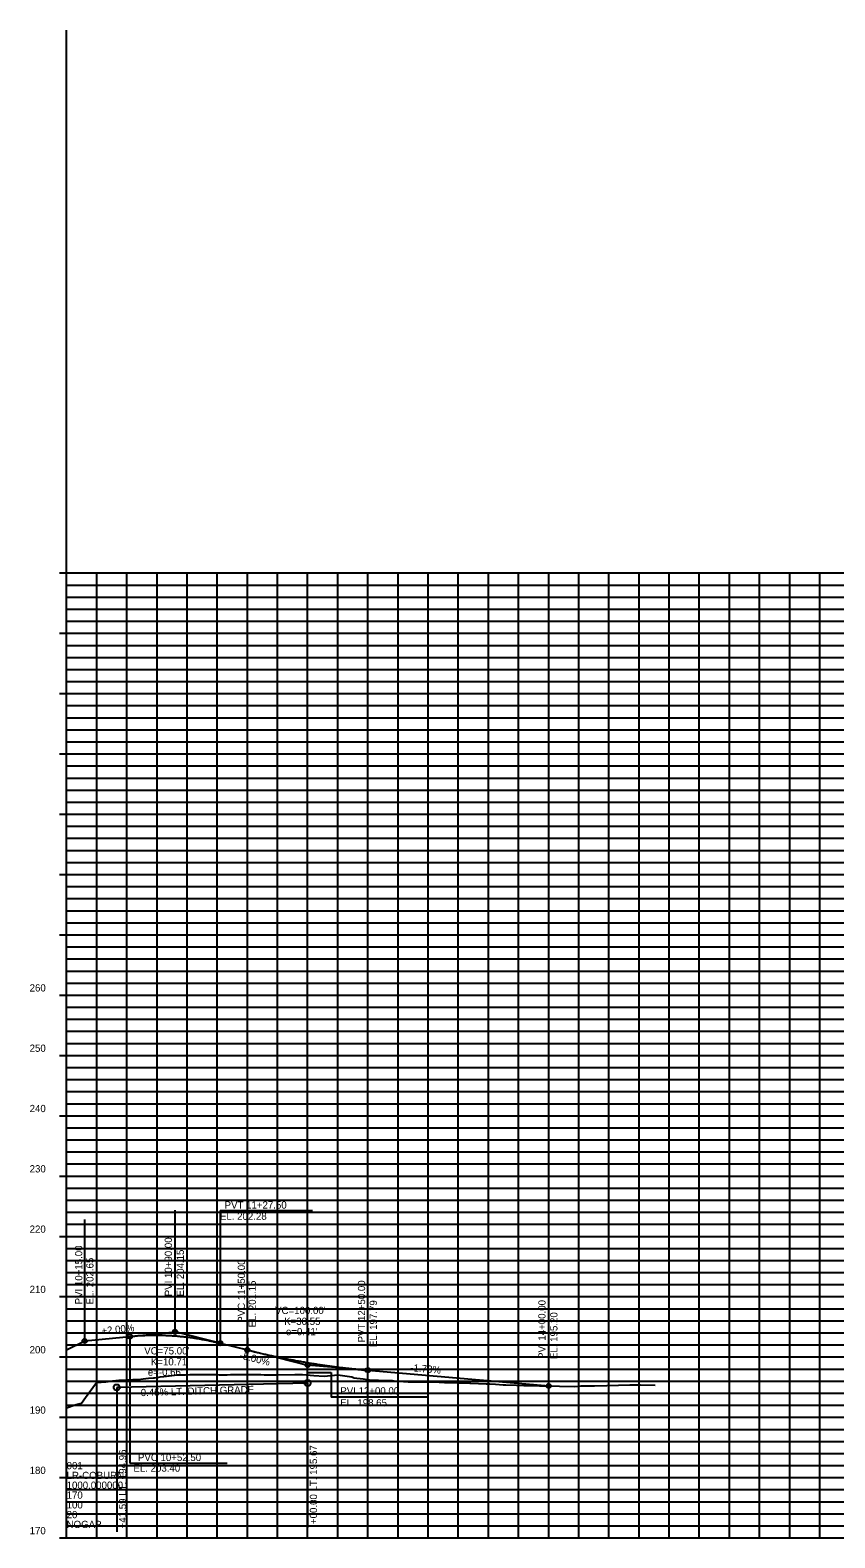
# Model space of a CAD drawing. Extents: x 1384498 to 1391279, y 1965973 to 1976560.
# Drawn here: x 1388619 to 1389286, y 1971310 to 1972560 of the extents above; entities that cross this region are included whole.
import ezdxf

# ---------------------------------------------------------------- set-up
doc = ezdxf.new("R2010")
doc.units = 0
for name, color, linetype in [('63', 7, 'Continuous'), ('Default', 7, 'Continuous'), ('R_Axis_Annotation', 7, 'Continuous'), ('R_Exist Surface', 7, 'Continuous'), ('R_Grid', 7, 'Continuous'), ('R_Grid Annot', 7, 'Continuous'), ('R_Grid_Minor', 7, 'Continuous'), ('R_Vert Alg', 7, 'Continuous'), ('R_Vert Alg Annot', 7, 'Continuous')]:
    doc.layers.add(name, color=color, linetype=linetype)

msp = doc.modelspace()

# ---------------------------------------------------------------- linework, layer by layer
at = {"layer": 'Default'}
msp.add_line((1388648.8, 1971309.8), (1388648.8, 1972559.8), dxfattribs=at)
at = {"layer": 'R_Exist Surface'}
for points in [[(1388648.8, 1971417.6), (1388656.8, 1971420.3), (1388661.1, 1971421.5), (1388664.5, 1971426.1), (1388673.5, 1971438.5), (1388681.3, 1971439.3), (1388686.8, 1971439.9), (1388692.4, 1971440.6), (1388695.1, 1971440.7), (1388698.9, 1971440.9), (1388699.4, 1971440.9), (1388703.8, 1971441), (1388707.9, 1971441.1), (1388708.1, 1971441.2), (1388712.4, 1971441.6), (1388716.7, 1971442.1), (1388721, 1971442.4), (1388721.6, 1971442.5), (1388724.3, 1971442.8), (1388725.3, 1971443), (1388726.4, 1971443.2), (1388729.6, 1971443.6), (1388733.9, 1971444.2), (1388738.2, 1971444.7), (1388740.5, 1971444.9), (1388742.5, 1971444.9), (1388745.9, 1971445), (1388746.8, 1971445), (1388747.5, 1971445), (1388751.1, 1971445.2), (1388751.3, 1971445.2), (1388754.2, 1971445.3), (1388755.5, 1971445.3), (1388757.6, 1971445.4), (1388759.8, 1971445.4), (1388761.1, 1971445.4), (1388764.1, 1971445.4), (1388768.4, 1971445.3), (1388772.7, 1971445.2), (1388775.5, 1971445.1), (1388776.4, 1971445.1), (1388777.1, 1971445.1), (1388777.4, 1971445.1), (1388777.8, 1971445.1), (1388782.1, 1971445.1), (1388784.7, 1971445.2), (1388786.9, 1971445.2), (1388791.6, 1971445.2), (1388791.6, 1971445.2), (1388791.7, 1971445.2), (1388796.2, 1971445.2), (1388798.3, 1971445.3), (1388800.8, 1971445.3), (1388804.9, 1971445.3), (1388805.5, 1971445.3), (1388806.7, 1971445.3), (1388809.3, 1971445.2), (1388810, 1971445.2), (1388812.8, 1971445.1), (1388814.6, 1971445.1), (1388816.3, 1971445), (1388819.1, 1971445), (1388819.8, 1971445), (1388822.3, 1971445), (1388823.2, 1971445), (1388823.4, 1971445), (1388838.2, 1971445.2), (1388841.8, 1971445.2), (1388844.6, 1971445.2), (1388853.8, 1971444.3), (1388862.5, 1971443.8), (1388873.8, 1971445.1), (1388885.5, 1971443.3), (1388886.1, 1971443), (1388886.9, 1971442.7), (1388887.2, 1971442.5), (1388895, 1971441.6), (1388902.2, 1971440.7), (1388907.6, 1971440.5), (1388912, 1971440.3), (1388917.3, 1971440.3), (1388918.8, 1971440.2), (1388920.2, 1971440.1), (1388932.3, 1971439.2), (1388932.7, 1971439.2), (1388939.4, 1971439.1), (1388945.3, 1971439.1), (1388947.4, 1971439.1), (1388957.9, 1971438.8), (1388962.4, 1971438.6), (1388968, 1971438.5), (1388968.4, 1971438.5), (1388968.7, 1971438.5), (1388973.7, 1971438.4), (1388976.5, 1971438.4), (1388983.5, 1971438.2), (1388984.2, 1971438.2), (1388997, 1971437.4), (1388997.8, 1971437.5), (1388998.6, 1971437.5), (1389000.1, 1971437.4)], [(1389000.1, 1971437.4), (1389004.6, 1971437.2), (1389011.1, 1971436.8), (1389013.3, 1971436.7), (1389022, 1971436.3), (1389028.3, 1971436.1), (1389031.6, 1971436.1), (1389034.7, 1971436.1), (1389041.1, 1971436), (1389041.5, 1971436), (1389042.9, 1971436), (1389043.5, 1971436), (1389057.8, 1971435.6), (1389070.2, 1971435.4), (1389075.4, 1971436), (1389086.8, 1971436), (1389097, 1971436.1), (1389106.8, 1971436.5), (1389116.1, 1971436.6), (1389125.1, 1971436.6), (1389137.2, 1971436.5)]]:
    msp.add_lwpolyline(points, dxfattribs=at)
at = {"layer": 'R_Grid'}
for p, q in [((1388648.8, 1971309.8), (1388648.8, 1972109.8)), ((1388648.8, 1972109.8), (1391248.8, 1972109.8)), ((1388648.8, 1972109.8), (1391248.8, 1972109.8)), ((1388748.8, 1971309.8), (1388748.8, 1972109.8)), ((1388848.8, 1971309.8), (1388848.8, 1972109.8)), ((1388948.8, 1971309.8), (1388948.8, 1972109.8)), ((1389048.8, 1971309.8), (1389048.8, 1972109.8)), ((1389148.8, 1971309.8), (1389148.8, 1972109.8)), ((1389248.8, 1971309.8), (1389248.8, 1972109.8)), ((1388648.8, 1972059.8), (1391248.8, 1972059.8)), ((1388648.8, 1972009.8), (1391248.8, 1972009.8)), ((1388648.8, 1971959.8), (1391248.8, 1971959.8)), ((1388648.8, 1971909.8), (1391248.8, 1971909.8)), ((1388648.8, 1971859.8), (1391248.8, 1971859.8)), ((1388648.8, 1971809.8), (1391248.8, 1971809.8)), ((1388648.8, 1971759.8), (1391248.8, 1971759.8)), ((1388648.8, 1971709.8), (1391248.8, 1971709.8)), ((1388648.8, 1971659.8), (1391248.8, 1971659.8)), ((1388648.8, 1971609.8), (1391248.8, 1971609.8)), ((1388648.8, 1971559.8), (1391248.8, 1971559.8)), ((1388648.8, 1971509.8), (1391248.8, 1971509.8)), ((1388648.8, 1971459.8), (1391248.8, 1971459.8)), ((1388648.8, 1971409.8), (1391248.8, 1971409.8)), ((1388648.8, 1971359.8), (1391248.8, 1971359.8)), ((1388648.8, 1971309.8), (1391248.8, 1971309.8))]:
    msp.add_line(p, q, dxfattribs=at)
at = {"layer": 'R_Grid Annot'}
for p, q in [((1388642.8, 1972109.8), (1388648.8, 1972109.8)), ((1388642.8, 1972109.8), (1388648.8, 1972109.8)), ((1388648.8, 1972099.8), (1388651.8, 1972099.8)), ((1388648.8, 1972089.8), (1388651.8, 1972089.8)), ((1388648.8, 1972079.8), (1388651.8, 1972079.8)), ((1388648.8, 1972069.8), (1388651.8, 1972069.8)), ((1388642.8, 1972059.8), (1388648.8, 1972059.8)), ((1388648.8, 1972049.8), (1388651.8, 1972049.8)), ((1388648.8, 1972039.8), (1388651.8, 1972039.8)), ((1388648.8, 1972029.8), (1388651.8, 1972029.8)), ((1388648.8, 1972019.8), (1388651.8, 1972019.8)), ((1388642.8, 1972009.8), (1388648.8, 1972009.8)), ((1388648.8, 1971999.8), (1388651.8, 1971999.8)), ((1388648.8, 1971989.8), (1388651.8, 1971989.8)), ((1388648.8, 1971979.8), (1388651.8, 1971979.8)), ((1388648.8, 1971969.8), (1388651.8, 1971969.8)), ((1388642.8, 1971959.8), (1388648.8, 1971959.8)), ((1388648.8, 1971949.8), (1388651.8, 1971949.8)), ((1388648.8, 1971939.8), (1388651.8, 1971939.8)), ((1388648.8, 1971929.8), (1388651.8, 1971929.8)), ((1388648.8, 1971919.8), (1388651.8, 1971919.8)), ((1388642.8, 1971909.8), (1388648.8, 1971909.8)), ((1388648.8, 1971899.8), (1388651.8, 1971899.8)), ((1388648.8, 1971889.8), (1388651.8, 1971889.8)), ((1388648.8, 1971879.8), (1388651.8, 1971879.8)), ((1388648.8, 1971869.8), (1388651.8, 1971869.8)), ((1388642.8, 1971859.8), (1388648.8, 1971859.8)), ((1388648.8, 1971849.8), (1388651.8, 1971849.8)), ((1388648.8, 1971839.8), (1388651.8, 1971839.8)), ((1388648.8, 1971829.8), (1388651.8, 1971829.8)), ((1388648.8, 1971819.8), (1388651.8, 1971819.8)), ((1388642.8, 1971809.8), (1388648.8, 1971809.8)), ((1388648.8, 1971799.8), (1388651.8, 1971799.8)), ((1388648.8, 1971789.8), (1388651.8, 1971789.8)), ((1388648.8, 1971779.8), (1388651.8, 1971779.8)), ((1388648.8, 1971769.8), (1388651.8, 1971769.8)), ((1388642.8, 1971759.8), (1388648.8, 1971759.8)), ((1388648.8, 1971749.8), (1388651.8, 1971749.8)), ((1388648.8, 1971739.8), (1388651.8, 1971739.8)), ((1388648.8, 1971729.8), (1388651.8, 1971729.8)), ((1388648.8, 1971719.8), (1388651.8, 1971719.8)), ((1388642.8, 1971709.8), (1388648.8, 1971709.8)), ((1388648.8, 1971699.8), (1388651.8, 1971699.8)), ((1388648.8, 1971689.8), (1388651.8, 1971689.8)), ((1388648.8, 1971679.8), (1388651.8, 1971679.8)), ((1388648.8, 1971669.8), (1388651.8, 1971669.8)), ((1388642.8, 1971659.8), (1388648.8, 1971659.8)), ((1388648.8, 1971649.8), (1388651.8, 1971649.8)), ((1388648.8, 1971639.8), (1388651.8, 1971639.8)), ((1388648.8, 1971629.8), (1388651.8, 1971629.8)), ((1388648.8, 1971619.8), (1388651.8, 1971619.8)), ((1388642.8, 1971609.8), (1388648.8, 1971609.8)), ((1388648.8, 1971599.8), (1388651.8, 1971599.8)), ((1388648.8, 1971589.8), (1388651.8, 1971589.8)), ((1388648.8, 1971579.8), (1388651.8, 1971579.8)), ((1388648.8, 1971569.8), (1388651.8, 1971569.8)), ((1388642.8, 1971559.8), (1388648.8, 1971559.8)), ((1388648.8, 1971549.8), (1388651.8, 1971549.8)), ((1388648.8, 1971539.8), (1388651.8, 1971539.8)), ((1388648.8, 1971529.8), (1388651.8, 1971529.8)), ((1388648.8, 1971519.8), (1388651.8, 1971519.8)), ((1388642.8, 1971509.8), (1388648.8, 1971509.8)), ((1388648.8, 1971499.8), (1388651.8, 1971499.8)), ((1388648.8, 1971489.8), (1388651.8, 1971489.8)), ((1388648.8, 1971479.8), (1388651.8, 1971479.8)), ((1388648.8, 1971469.8), (1388651.8, 1971469.8)), ((1388642.8, 1971459.8), (1388648.8, 1971459.8)), ((1388648.8, 1971449.8), (1388651.8, 1971449.8)), ((1388648.8, 1971439.8), (1388651.8, 1971439.8)), ((1388648.8, 1971429.8), (1388651.8, 1971429.8)), ((1388648.8, 1971419.8), (1388651.8, 1971419.8)), ((1388642.8, 1971409.8), (1388648.8, 1971409.8)), ((1388648.8, 1971399.8), (1388651.8, 1971399.8)), ((1388648.8, 1971389.8), (1388651.8, 1971389.8)), ((1388648.8, 1971379.8), (1388651.8, 1971379.8)), ((1388648.8, 1971369.8), (1388651.8, 1971369.8)), ((1388642.8, 1971359.8), (1388648.8, 1971359.8)), ((1388648.8, 1971349.8), (1388651.8, 1971349.8)), ((1388648.8, 1971339.8), (1388651.8, 1971339.8)), ((1388648.8, 1971329.8), (1388651.8, 1971329.8)), ((1388648.8, 1971319.8), (1388651.8, 1971319.8)), ((1388642.8, 1971309.8), (1388648.8, 1971309.8))]:
    msp.add_line(p, q, dxfattribs=at)
at = {"layer": 'R_Grid_Minor'}
for p, q in [((1388673.8, 1971309.8), (1388673.8, 1972109.8)), ((1388698.8, 1971309.8), (1388698.8, 1972109.8)), ((1388723.8, 1971309.8), (1388723.8, 1972109.8)), ((1388773.8, 1971309.8), (1388773.8, 1972109.8)), ((1388798.8, 1971309.8), (1388798.8, 1972109.8)), ((1388823.8, 1971309.8), (1388823.8, 1972109.8)), ((1388873.8, 1971309.8), (1388873.8, 1972109.8)), ((1388898.8, 1971309.8), (1388898.8, 1972109.8)), ((1388923.8, 1971309.8), (1388923.8, 1972109.8)), ((1388973.8, 1971309.8), (1388973.8, 1972109.8)), ((1388998.8, 1971309.8), (1388998.8, 1972109.8)), ((1389023.8, 1971309.8), (1389023.8, 1972109.8)), ((1389073.8, 1971309.8), (1389073.8, 1972109.8)), ((1389098.8, 1971309.8), (1389098.8, 1972109.8)), ((1389123.8, 1971309.8), (1389123.8, 1972109.8)), ((1389173.8, 1971309.8), (1389173.8, 1972109.8)), ((1389198.8, 1971309.8), (1389198.8, 1972109.8)), ((1389223.8, 1971309.8), (1389223.8, 1972109.8)), ((1389273.8, 1971309.8), (1389273.8, 1972109.8)), ((1388648.8, 1972099.8), (1391248.8, 1972099.8)), ((1388648.8, 1972089.8), (1391248.8, 1972089.8)), ((1388648.8, 1972079.8), (1391248.8, 1972079.8)), ((1388648.8, 1972069.8), (1391248.8, 1972069.8)), ((1388648.8, 1972049.8), (1391248.8, 1972049.8)), ((1388648.8, 1972039.8), (1391248.8, 1972039.8)), ((1388648.8, 1972029.8), (1391248.8, 1972029.8)), ((1388648.8, 1972019.8), (1391248.8, 1972019.8)), ((1388648.8, 1971999.8), (1391248.8, 1971999.8)), ((1388648.8, 1971989.8), (1391248.8, 1971989.8)), ((1388648.8, 1971979.8), (1391248.8, 1971979.8)), ((1388648.8, 1971969.8), (1391248.8, 1971969.8)), ((1388648.8, 1971949.8), (1391248.8, 1971949.8)), ((1388648.8, 1971939.8), (1391248.8, 1971939.8)), ((1388648.8, 1971929.8), (1391248.8, 1971929.8)), ((1388648.8, 1971919.8), (1391248.8, 1971919.8)), ((1388648.8, 1971899.8), (1391248.8, 1971899.8)), ((1388648.8, 1971889.8), (1391248.8, 1971889.8)), ((1388648.8, 1971879.8), (1391248.8, 1971879.8)), ((1388648.8, 1971869.8), (1391248.8, 1971869.8)), ((1388648.8, 1971849.8), (1391248.8, 1971849.8)), ((1388648.8, 1971839.8), (1391248.8, 1971839.8)), ((1388648.8, 1971829.8), (1391248.8, 1971829.8)), ((1388648.8, 1971819.8), (1391248.8, 1971819.8)), ((1388648.8, 1971799.8), (1391248.8, 1971799.8)), ((1388648.8, 1971789.8), (1391248.8, 1971789.8)), ((1388648.8, 1971779.8), (1391248.8, 1971779.8)), ((1388648.8, 1971769.8), (1391248.8, 1971769.8)), ((1388648.8, 1971749.8), (1391248.8, 1971749.8)), ((1388648.8, 1971739.8), (1391248.8, 1971739.8)), ((1388648.8, 1971729.8), (1391248.8, 1971729.8)), ((1388648.8, 1971719.8), (1391248.8, 1971719.8)), ((1388648.8, 1971699.8), (1391248.8, 1971699.8)), ((1388648.8, 1971689.8), (1391248.8, 1971689.8)), ((1388648.8, 1971679.8), (1391248.8, 1971679.8)), ((1388648.8, 1971669.8), (1391248.8, 1971669.8)), ((1388648.8, 1971649.8), (1391248.8, 1971649.8)), ((1388648.8, 1971639.8), (1391248.8, 1971639.8)), ((1388648.8, 1971629.8), (1391248.8, 1971629.8)), ((1388648.8, 1971619.8), (1391248.8, 1971619.8)), ((1388648.8, 1971599.8), (1391248.8, 1971599.8)), ((1388648.8, 1971589.8), (1391248.8, 1971589.8)), ((1388648.8, 1971579.8), (1391248.8, 1971579.8)), ((1388648.8, 1971569.8), (1391248.8, 1971569.8)), ((1388648.8, 1971549.8), (1391248.8, 1971549.8)), ((1388648.8, 1971539.8), (1391248.8, 1971539.8)), ((1388648.8, 1971529.8), (1391248.8, 1971529.8)), ((1388648.8, 1971519.8), (1391248.8, 1971519.8)), ((1388648.8, 1971499.8), (1391248.8, 1971499.8)), ((1388648.8, 1971489.8), (1391248.8, 1971489.8)), ((1388648.8, 1971479.8), (1391248.8, 1971479.8)), ((1388648.8, 1971469.8), (1391248.8, 1971469.8)), ((1388648.8, 1971449.8), (1391248.8, 1971449.8)), ((1388648.8, 1971439.8), (1391248.8, 1971439.8)), ((1388648.8, 1971429.8), (1391248.8, 1971429.8)), ((1388648.8, 1971419.8), (1391248.8, 1971419.8)), ((1388648.8, 1971399.8), (1391248.8, 1971399.8)), ((1388648.8, 1971389.8), (1391248.8, 1971389.8)), ((1388648.8, 1971379.8), (1391248.8, 1971379.8)), ((1388648.8, 1971369.8), (1391248.8, 1971369.8)), ((1388648.8, 1971349.8), (1391248.8, 1971349.8)), ((1388648.8, 1971339.8), (1391248.8, 1971339.8)), ((1388648.8, 1971329.8), (1391248.8, 1971329.8)), ((1388648.8, 1971319.8), (1391248.8, 1971319.8))]:
    msp.add_line(p, q, dxfattribs=at)
at = {"layer": 'R_Vert Alg'}
for p, q in [((1388663.8, 1971473.1), (1388701.3, 1971476.8)), ((1388648.8, 1971465.6), (1388663.8, 1971473.1)), ((1388776.3, 1971471.2), (1388798.8, 1971465.6)), ((1388848.8, 1971438.2), (1388690.4, 1971434.6)), ((1388898.8, 1971448.8), (1389048.8, 1971435.8))]:
    msp.add_line(p, q, dxfattribs=at)
for points in [[(1388701.3, 1971476.8), (1388702.8, 1971477), (1388704.3, 1971477.1), (1388705.8, 1971477.2), (1388707.3, 1971477.4), (1388708.8, 1971477.5), (1388710.3, 1971477.5), (1388711.8, 1971477.6), (1388713.3, 1971477.7), (1388714.8, 1971477.8), (1388716.3, 1971477.8), (1388717.8, 1971477.9), (1388719.3, 1971477.9), (1388720.8, 1971477.9), (1388722.3, 1971477.9), (1388723.8, 1971477.9), (1388725.3, 1971477.9), (1388726.8, 1971477.9), (1388728.3, 1971477.8), (1388729.8, 1971477.8), (1388731.3, 1971477.7), (1388732.8, 1971477.7), (1388734.3, 1971477.6), (1388735.8, 1971477.5), (1388737.3, 1971477.4), (1388738.8, 1971477.3), (1388740.3, 1971477.2), (1388741.8, 1971477.1), (1388743.3, 1971476.9), (1388744.8, 1971476.8), (1388746.3, 1971476.6), (1388747.8, 1971476.4), (1388749.3, 1971476.3), (1388750.8, 1971476.1), (1388752.3, 1971475.9), (1388753.8, 1971475.7), (1388755.3, 1971475.4), (1388756.8, 1971475.2), (1388758.3, 1971475), (1388759.8, 1971474.7), (1388761.3, 1971474.4), (1388762.8, 1971474.2), (1388764.3, 1971473.9), (1388765.8, 1971473.6), (1388767.3, 1971473.3), (1388768.8, 1971473), (1388770.3, 1971472.6), (1388771.8, 1971472.3), (1388773.3, 1971471.9), (1388774.8, 1971471.6), (1388776.3, 1971471.2)], [(1388798.8, 1971465.6), (1388800.8, 1971465.1), (1388802.8, 1971464.6), (1388804.8, 1971464.1), (1388806.8, 1971463.6), (1388808.8, 1971463.2), (1388810.8, 1971462.7), (1388812.8, 1971462.2), (1388814.8, 1971461.8), (1388816.8, 1971461.4), (1388818.8, 1971460.9), (1388820.8, 1971460.5), (1388822.8, 1971460.1), (1388824.8, 1971459.6), (1388826.8, 1971459.2), (1388828.8, 1971458.8), (1388830.8, 1971458.4), (1388832.8, 1971458), (1388834.8, 1971457.6), (1388836.8, 1971457.3), (1388838.8, 1971456.9), (1388840.8, 1971456.5), (1388842.8, 1971456.2), (1388844.8, 1971455.8), (1388846.8, 1971455.5), (1388848.8, 1971455.1), (1388850.8, 1971454.8), (1388852.8, 1971454.5), (1388854.8, 1971454.2), (1388856.8, 1971453.8), (1388858.8, 1971453.5), (1388860.8, 1971453.2), (1388862.8, 1971452.9), (1388864.8, 1971452.7), (1388866.8, 1971452.4), (1388868.8, 1971452.1), (1388870.8, 1971451.8), (1388872.8, 1971451.6), (1388874.8, 1971451.3), (1388876.8, 1971451.1), (1388878.8, 1971450.8), (1388880.8, 1971450.6), (1388882.8, 1971450.4), (1388884.8, 1971450.1), (1388886.8, 1971449.9), (1388888.8, 1971449.7), (1388890.8, 1971449.5), (1388892.8, 1971449.3), (1388894.8, 1971449.1), (1388896.8, 1971448.9), (1388898.8, 1971448.8)]]:
    msp.add_spline(points, degree=3, dxfattribs=at)
at = {"layer": 'R_Vert Alg Annot'}
for p, q in [((1388738.8, 1971490.6), (1388738.8, 1971581.4)), ((1388776.3, 1971581.1), (1388776.3, 1971471.2)), ((1388776.3, 1971581.1), (1388852.7, 1971581.1)), ((1388663.8, 1971483.1), (1388663.8, 1971573.9)), ((1388798.8, 1971475.6), (1388798.8, 1971559.6)), ((1388898.8, 1971458.8), (1388898.8, 1971542.8)), ((1389048.8, 1971445), (1389048.8, 1971529)), ((1388738.8, 1971480.6), (1388738.8, 1971490.6)), ((1388663.8, 1971473.1), (1388663.8, 1971483.1)), ((1388701.3, 1971476.8), (1388738.8, 1971480.6)), ((1388701.3, 1971476.8), (1388701.3, 1971435.9)), ((1388776.3, 1971471.2), (1388738.8, 1971480.6)), ((1388798.8, 1971475.6), (1388798.8, 1971465.6)), ((1388798.8, 1971465.6), (1388848.8, 1971453.1)), ((1388898.8, 1971448.8), (1388848.8, 1971453.1)), ((1388848.8, 1971447), (1388848.8, 1971453.1)), ((1388898.8, 1971448.8), (1388898.8, 1971458.8)), ((1388848.8, 1971447), (1388868.4, 1971447)), ((1388848.8, 1971438.2), (1388848.8, 1971318.3)), ((1388868.4, 1971447), (1388868.4, 1971426.5)), ((1389048.8, 1971435.8), (1389048.8, 1971445)), ((1388690.4, 1971434.6), (1388690.4, 1971314.7)), ((1388701.3, 1971433.8), (1388701.3, 1971371.7)), ((1388947.6, 1971426.5), (1388868.4, 1971426.5)), ((1388701.3, 1971371.7), (1388781.9, 1971371.7))]:
    msp.add_line(p, q, dxfattribs=at)
for centre, radius in [((1388701.3, 1971476.8), 1.85), ((1388738.8, 1971480.6), 1.85), ((1388663.8, 1971473.1), 1.85), ((1388776.3, 1971471.2), 1.85), ((1388798.8, 1971465.6), 1.85), ((1388848.8, 1971453.1), 1.85), ((1388898.8, 1971448.8), 1.85), ((1388848.8, 1971438.2), 2.5), ((1389048.8, 1971435.8), 1.85), ((1388690.4, 1971434.6), 2.5)]:
    msp.add_circle(centre, radius, dxfattribs=at)

# ---------------------------------------------------------------- texts
at = {"layer": '63'}
msp.add_text('-', height=0.0001, dxfattribs=at).set_placement((1388648.8, 1971309.8))
at = {"layer": 'Default'}
for s, p in [('001', (1388648.8, 1971366.7)), ('LR-COBURN', (1388648.8, 1971358.6)), ('1000.000000', (1388648.8, 1971350.5)), ('170', (1388648.8, 1971342.3)), ('100', (1388648.8, 1971334.2)), ('20', (1388648.8, 1971326.1)), ('NOGAP', (1388648.8, 1971318))]:
    msp.add_text(s, height=6, dxfattribs=at).set_placement(p)
at = {"layer": 'R_Axis_Annotation'}
for s, p in [('260', (1388618.1, 1971762.8)), ('250', (1388618.1, 1971712.8)), ('240', (1388618.1, 1971662.8)), ('230', (1388618.1, 1971612.8)), ('220', (1388618.1, 1971562.8)), ('210', (1388618.1, 1971512.8)), ('200', (1388618.1, 1971462.8)), ('190', (1388618.1, 1971412.8)), ('180', (1388618.1, 1971362.8)), ('170', (1388618.1, 1971312.8))]:
    msp.add_text(s, height=6, dxfattribs=at).set_placement(p)
at = {"layer": 'R_Vert Alg Annot'}
for s, rotation, p in [('PVT 11+27.50', 360, (1388779.9, 1971582.8)), (' EL. 202.28', 360, (1388773.8, 1971573.5)), ('PVI 10+15.00', 90, (1388661.8, 1971503.4)), ('PVI 10+90.00', 90, (1388736.2, 1971510.1)), ('EL. 202.65', 90, (1388671.1, 1971503.3)), ('EL. 204.15', 90, (1388746.1, 1971510)), ('PVC 11+50.00', 90, (1388796.8, 1971488.2)), (' EL. 201.15', 90, (1388805.8, 1971482.1)), ('PVT 12+50.00', 90, (1388896.5, 1971471.8)), (' EL. 197.79', 90, (1388906.3, 1971465.8)), ('PVI 14+00.00', 90, (1389046.2, 1971458.2)), ('EL. 195.20', 90, (1389056.1, 1971458.1)), ('+2.00%', 5.7106, (1388678, 1971478.4)), ('-5.00%', 345.9638, (1388792.1, 1971458.6)), ('-1.73%', 355.0667, (1388933.8, 1971448.1)), ('0.45% LT. DITCH GRADE', 1.6084, (1388710.4, 1971427.3)), ('PVI 12+00.00', 360, (1388875.9, 1971428.7)), ('EL. 198.65', 360, (1388875.8, 1971418.8)), ('+41.59 LT. 194.96', 90, (1388698.2, 1971317.7)), ('PVC 10+52.50', 360, (1388708, 1971373.5)), ('+00.00 LT. 195.67', 90, (1388856.6, 1971321.3)), (' EL. 203.40', 360, (1388702, 1971364.7))]:
    msp.add_text(s, height=6, rotation=rotation, dxfattribs=at).set_placement(p)
for s, p in [("VC=100.00'", (1388821.8, 1971495.4)), ('K=30.55', (1388829.3, 1971486.4)), ("e=0.41'", (1388830.8, 1971477.8)), ("VC=75.00'", (1388713.2, 1971461.9)), ("e=-0.66'", (1388716.2, 1971444.2)), ('K=10.71', (1388718.7, 1971452.8))]:
    msp.add_text(s, height=6, dxfattribs=at).set_placement(p)

doc.saveas('drawing.dxf')
